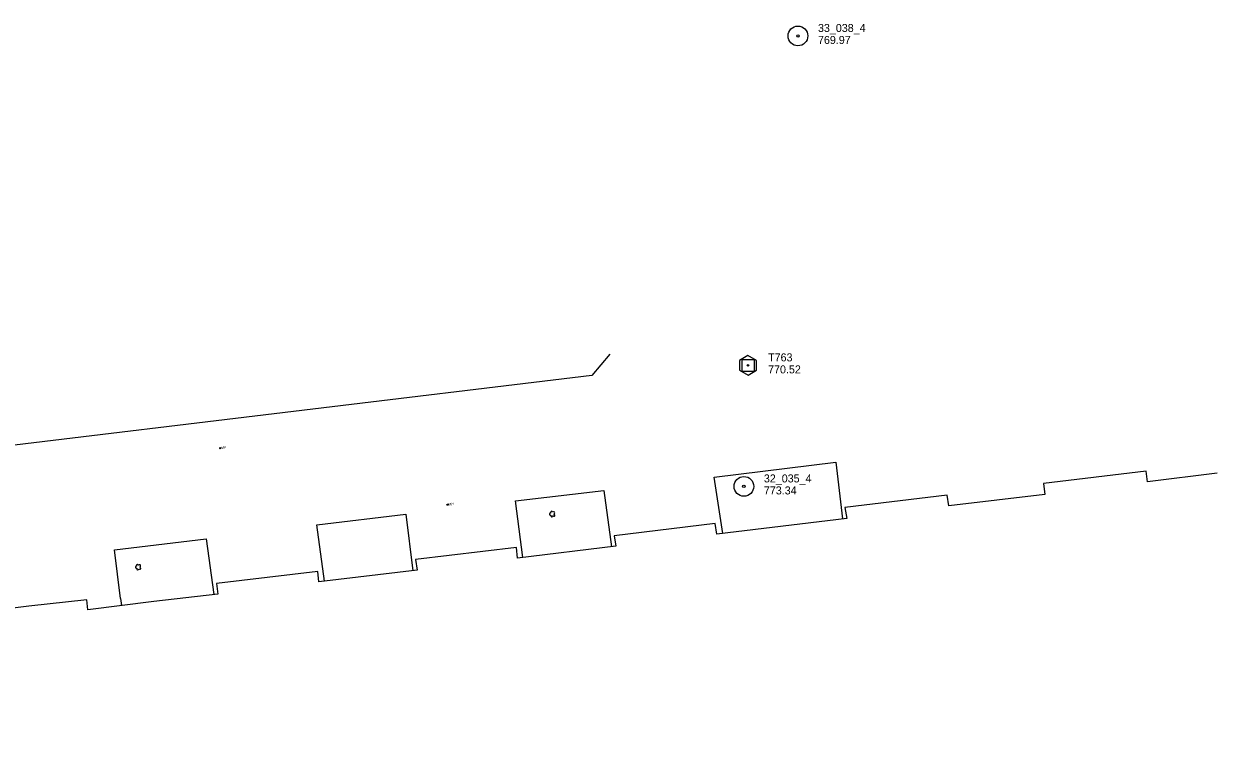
# Model space of a CAD drawing. Extents: x 589250 to 1188077, y 162953 to 363065.
# Drawn here: x 591127 to 592021, y 174822 to 175370 of the extents above; entities that cross this region are included whole.
import ezdxf

# ---------------------------------------------------------------- set-up
doc = ezdxf.new("R2010")
doc.units = 0
for name, color, linetype in [('E_MAP_Control', 7, 'Continuous'), ('E_MAP_PassPoints', 7, 'Continuous'), ('Level 12', 7, 'Continuous'), ('Level 16', 7, 'Continuous'), ('Level 17', 7, 'Continuous'), ('Level 18', 7, 'Continuous')]:
    doc.layers.add(name, color=color, linetype=linetype)

# ---------------------------------------------------------------- blocks, each defined once
blk = doc.blocks.new('TREE')
at = {"layer": 'Level 18'}
for centre, major_axis, ratio in [((-1.15, 0.04), (0.987, -0.025), 0.832022), ((-0.35, 1.07), (0.272, -0.996), 0.782863), ((0.84, 0.55), (-1.05, -0.59), 0.691916), ((-0.47, -1.04), (0.361, 0.971), 0.716896), ((0.73, -0.74), (-1, 0.92), 0.560249)]:
    blk.add_ellipse(centre, major_axis=major_axis, ratio=ratio, start_param=1.570796, end_param=4.712389, dxfattribs=at)
blk = doc.blocks.new('MH_1')
at = {"layer": 'Level 16'}
for centre, radius in [((0.01, 0), 0.45), ((0.01, 0), 0.365), ((0.01, 0), 0.29), ((0, 0), 0.182)]:
    blk.add_circle(centre, radius, dxfattribs=at)
blk.add_text('MH', height=1.8, rotation=359.99997, dxfattribs=at).set_placement((0.76, -0.74))

msp = doc.modelspace()

# ---------------------------------------------------------------- linework, layer by layer
at = {"layer": 'E_MAP_Control'}
for p, q in [((591665.24, 175108.92), (591665.24, 175117.92)), ((591665.24, 175117.92), (591674.24, 175117.92)), ((591674.24, 175117.92), (591674.24, 175108.92)), ((591674.24, 175108.92), (591665.24, 175108.92))]:
    msp.add_line(p, q, dxfattribs=at)
msp.add_lwpolyline([(591663.33, 175117.18), (591663.33, 175109.79), (591669.79, 175106.06), (591676.18, 175109.73), (591676.18, 175117.06), (591669.66, 175120.78)], close=True, dxfattribs=at)
msp.add_circle((591669.74, 175113.42), 0.546, dxfattribs=at)
at = {"layer": 'E_MAP_PassPoints'}
for centre, radius in [((591707.14, 175360.52), 7.38), ((591707.14, 175360.52), 0.945), ((591666.6, 175022.65), 7.38), ((591666.6, 175022.65), 0.945)]:
    msp.add_circle(centre, radius, dxfattribs=at)
at = {"layer": 'Level 12'}
for points in [[(592021.33, 175032.52), (591969.11, 175026.16), (591968.08, 175034.04), (591891.29, 175024.92), (591892.28, 175016.62), (591820.31, 175007.95), (591819.06, 175016.12), (591742.3, 175006.77), (591743.68, 174998.67), (591646.21, 174986.89), (591645.1, 174994.87), (591569.5, 174985.69), (591570.69, 174977.78), (591496.98, 174968.92), (591496.18, 174976.88), (591420.55, 174967.76), (591421.62, 174959.74), (591348.1, 174951.05), (591347.22, 174958.71), (591271.39, 174949.74), (591272.19, 174941.77), (591224.27, 174936.38), (591174.81, 174929.94), (591174.07, 174937.65), (591130.74, 174932.81)], [(591130.74, 174932.81), (591092.55, 174928.14), (591093.55, 174919.93), (591025.6, 174911.64), (591024.65, 174919.48), (590949.2, 174910.28), (590950.16, 174902.43), (590900.79, 174896.41), (590931.19, 174647.24), (591157.73, 174674.88)]]:
    msp.add_lwpolyline(points, dxfattribs=at)
at = {"layer": 'Level 17'}
for points in [[(591566.05, 175121.88), (591552.67, 175105.81), (591105.14, 175051.8), (591102.87, 175051.82), (591102.19, 175052.27), (591101.5, 175053.02), (591101.05, 175053.77), (591100.19, 175055.27), (591098.41, 175061.03), (591097.73, 175066.08)], [(591650.74, 174987.43), (591644.33, 175029.67), (591735.56, 175040.75), (591740.45, 174998.28)], [(591501.03, 174969.4), (591495.46, 175011.78), (591561.72, 175019.66), (591567.49, 174977.39)], [(591352.17, 174951.53), (591346.5, 174993.81), (591413.23, 175001.84), (591418.58, 174959.38)], [(591199.3, 174938.64), (591194.97, 174975.02), (591263.58, 174983.43), (591269.42, 174941.46)], [(591199.3, 174938.64), (591200.08, 174933.23), (591200.01, 174933.78)]]:
    msp.add_lwpolyline(points, dxfattribs=at)

# ---------------------------------------------------------------- block references
at = {"layer": 'Level 16', "rotation": 7.005851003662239}
for p in [(591274.1, 175051.28), (591444.52, 175008.9)]:
    msp.add_blockref('MH_1', p, dxfattribs=at)
at = {"layer": 'Level 18', "rotation": 7.005851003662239}
for p in [(591522.99, 175001.96), (591212.62, 174962.14)]:
    msp.add_blockref('TREE', p, dxfattribs=at)

# ---------------------------------------------------------------- texts
at = {"layer": 'E_MAP_Control'}
for s, p in [('T763', (591684.75, 175116.42)), ('770.52', (591684.75, 175107.42))]:
    msp.add_text(s, height=6, dxfattribs=at).set_placement(p)
at = {"layer": 'E_MAP_PassPoints'}
for s, p in [('33_038_4', (591722.14, 175363.51)), ('769.97', (591722.14, 175354.51)), ('32_035_4', (591681.6, 175025.63)), ('773.34', (591681.6, 175016.63))]:
    msp.add_text(s, height=6, dxfattribs=at).set_placement(p)
at = {"layer": 'Level 16'}
msp.add_text('HI THERE', height=0.161, rotation=358.42339, dxfattribs=at).set_placement((591273.57, 175051.14))

doc.saveas('drawing.dxf')
